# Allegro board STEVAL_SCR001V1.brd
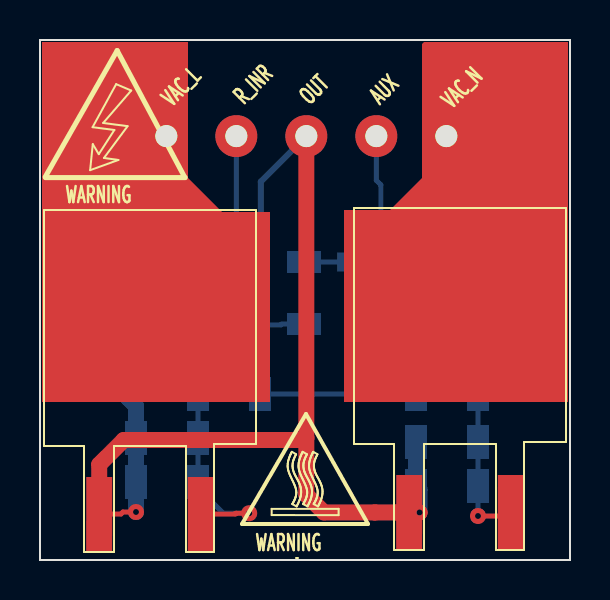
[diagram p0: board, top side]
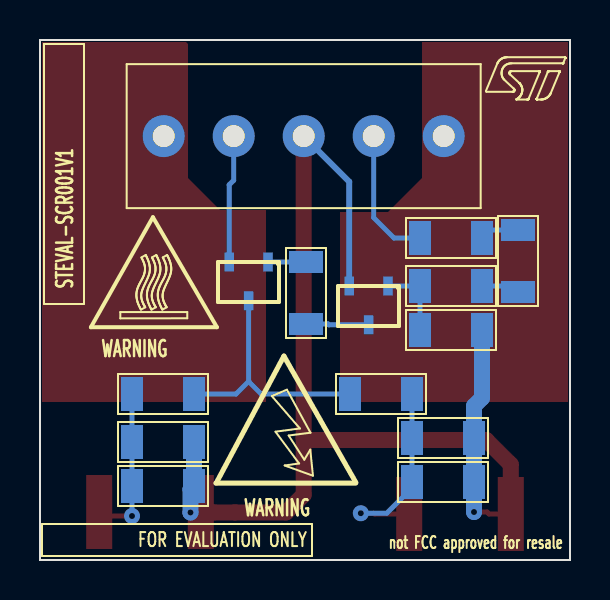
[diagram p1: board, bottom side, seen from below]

Outline 26.5 x 26 mm; copper layers: TOP, BOTTOM. Coordinates in mm from the lower left corner of the outline.
Outline path: 0,26 0,0 ; 0,26 26.5,26 ; 0,26 0,0 ; 0,26 26.5,26 ; 0,0 26.5,0 ; 0,0 26.5,0 ; 26.5,26 26.5,0 ; 26.5,26 26.5,0

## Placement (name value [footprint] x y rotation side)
C1  res_1206  [RES_1206]  7.9 6.1 180 bottom
C2  res_1206  [RES_1206]  21.9 5.9 180 bottom
J1  connector  [CONNECTOR]  20.32 21.19 90 bottom
R1  res_1206  [RES_1206]  11 8.3 180 bottom
R2  res_1206  [RES_1206]  13.2 11.8 90 bottom
R4  res_1206  [RES_1206]  7.9 3.9 180 bottom
R5  res_1206  [RES_1206]  21.9 8.3 180 bottom
R6  res_1206  [RES_1206]  21.9 3.7 180 bottom
R8  res_1206  [RES_1206]  7.5 11.5 180 bottom
R9  res_1206  [RES_1206]  4.4 13.7 0 bottom
R10  res_1206  [RES_1206]  2.6 16.5 270 bottom
R11  res_1206  [RES_1206]  4.4 16.1 0 bottom
SCR1  d2pak_s  [D2PAK_S]  5.5 12.9 270 top
SCR2  d2pak_s  [D2PAK_S]  21 13 270 top
T1  -  [PNP]  15.1 14.9 270 bottom
T2  -  [PNP]  9.1 13.7 270 bottom

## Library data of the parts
C1 C2 R1 R2 R4-R6 R8-R11 = res_1206
J1 = connector_0
SCR1 SCR2 = d2pak_s
T1 T2 = PNP

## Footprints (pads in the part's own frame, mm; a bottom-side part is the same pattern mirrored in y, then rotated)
CONNECTOR
  round 2.1 hole 1.1: 1(0,0) 2(0,-3.5) 3(0,-7) 4(0,-10.5) 5(0,-14)
D2PAK_S
  rect 3.7x1.3 smd: 1(10.6,2.54) 2(10.6,-2.54)
  rect 8.9x10.3 smd: 3(0,0)
PNP
  rect 0.95x0.48 smd: 1(0,0) 2(1.94,-0.97) 3(0,-1.94)
RES_1206
  rect 1.1x1.7 smd: 1(0,0) 2(3.1,0)

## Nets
N14543: J1.1(L) SCR2.3(A)
N14550: J1.5(N) SCR1.3(A)
N14893: C1.1(A) R1.2(B) R4.1(A) SCR1.1(G)
N14904: C1.2(B) C2.2(B) J1.3(OUT) R4.2(B) R6.2(B) R8.2(B) SCR1.2(K) SCR2.2(K) T2.3(E)
N15019: C2.1(A) R5.1(A) R6.1(A) SCR2.1(G)
N15128: R1.1(A) R5.2(B) T1.2(C)
N15355: R2.2(B) T1.1(B)
N15359: R2.1(A) T2.2(C)
N15568: R8.1(A) R9.2(B) T2.1(B)
N16008: J1.2(AUX) T1.3(E)
N16371: R10.1(A) R11.1(A)
N16375: J1.4(NTC_HIGH) R11.2(B)
N16475: R9.1(A) R10.2(B)

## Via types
v1: diameter 0.8, hole 0.3, TOP to BOTTOM, 4 vias

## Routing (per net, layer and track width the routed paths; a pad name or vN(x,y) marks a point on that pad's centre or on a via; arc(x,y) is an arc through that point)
N14550: length 0.1
  TOP w0.5: 6.41,12.94 6.32,13.03
N14893: length 10.2
  TOP w0.25: SCR1.1 9.77,2.3 9.81,2.34 v1(10.46,2.34)
  BOTTOM w0.25: v1(10.46,2.34) 9.16,2.34 7.9,3.6 R4.1 C1.1 R1.2
N14904: length 60.7
  TOP w0.25: SCR1.2 4.05,2.3 4.15,2.4 v1(4.8,2.4)
  TOP w0.8: SCR1.2 2.96,4.77 4.19,6 13.22,6 13.32,6.1 ; 13.32,6.1 13.32,3.26 14.2,2.38 16.75,2.38 17.78,2.38 18.68,2.38 v1(18.98,2.38) ; 13.32,6.1 J1.3
  BOTTOM w0.3: T2.3 11.04,18.92 J1.3
  BOTTOM w0.8: 18.68,3.58 R6.2 ; R6.2 18.98,3.52 v1(18.98,2.38) ; R6.2 C2.2 ; R8.2 4.4,8.1 4.8,7.7 C1.2 R4.2 v1(4.8,2.4)
N15019: length 7.8
  TOP w0.25: v1(21.9,2.2) 23.34,2.2 SCR2.1
  BOTTOM w0.25: v1(21.9,2.2) R6.1 C2.1 R5.1
N15128: length 12.4
  BOTTOM w0.25: 16.07,8.93 16.7,8.3 R5.2 ; 16.07,8.93 15.44,8.3 R1.1 ; 16.07,8.93 T1.2
N15355: length 1.9
  BOTTOM w0.25: R2.2 T1.1
N15359: length 3.1
  BOTTOM w0.25: T2.2 12.06,11.76 12.1,11.8 R2.1
N15568: length 3.8
  BOTTOM w0.25: T2.1 R9.2 R8.1
N16008: length 6.4
  BOTTOM w0.25: T1.3 17.04,18.76 16.82,18.98 J1.2
N16371: length 2
  BOTTOM w0.25: R10.1 4,16.5 R11.1
N16375: length 6.8
  BOTTOM w0.25: R11.2 8.8,16.1 9.82,17.12 J1.4
N16475: length 1.9
  BOTTOM w0.25: R9.1 2.9,13.7 R10.2

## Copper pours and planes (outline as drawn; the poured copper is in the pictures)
N14543 on TOP (solid shape): 26.4,7.9 15.2,7.9 15.2,17.5 17.5,17.5 19.1,19.1 19.1,25.8 19.2,25.9 26.4,25.9
N14550 on TOP (solid shape): 7.4,19.1 9.1,17.4 11.5,17.4 11.5,7.9 0.1,7.9 0.1,25.9 7.4,25.9

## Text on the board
Ref Des/Silkscreen Bottom: not FCC approved for resale | FOR EVALUATION ONLY | WARNING | STEVAL-SCR001V1
Ref Des/Silkscreen Top: WARNING | VAC_L | R_INR | OUT | AUX | VAC_N
